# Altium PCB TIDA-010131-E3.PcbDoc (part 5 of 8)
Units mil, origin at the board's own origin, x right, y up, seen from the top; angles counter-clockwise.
Board outline 6889.76 x 5118.11 mil, 6 copper layers (Top Layer, GND Layer, Signal Layer 1, Signal Layer 2, PWR Layer, Bottom Layer), stack 58.5 mil thick; 758 components, 455 nets, 2194 pads, 1156 vias.
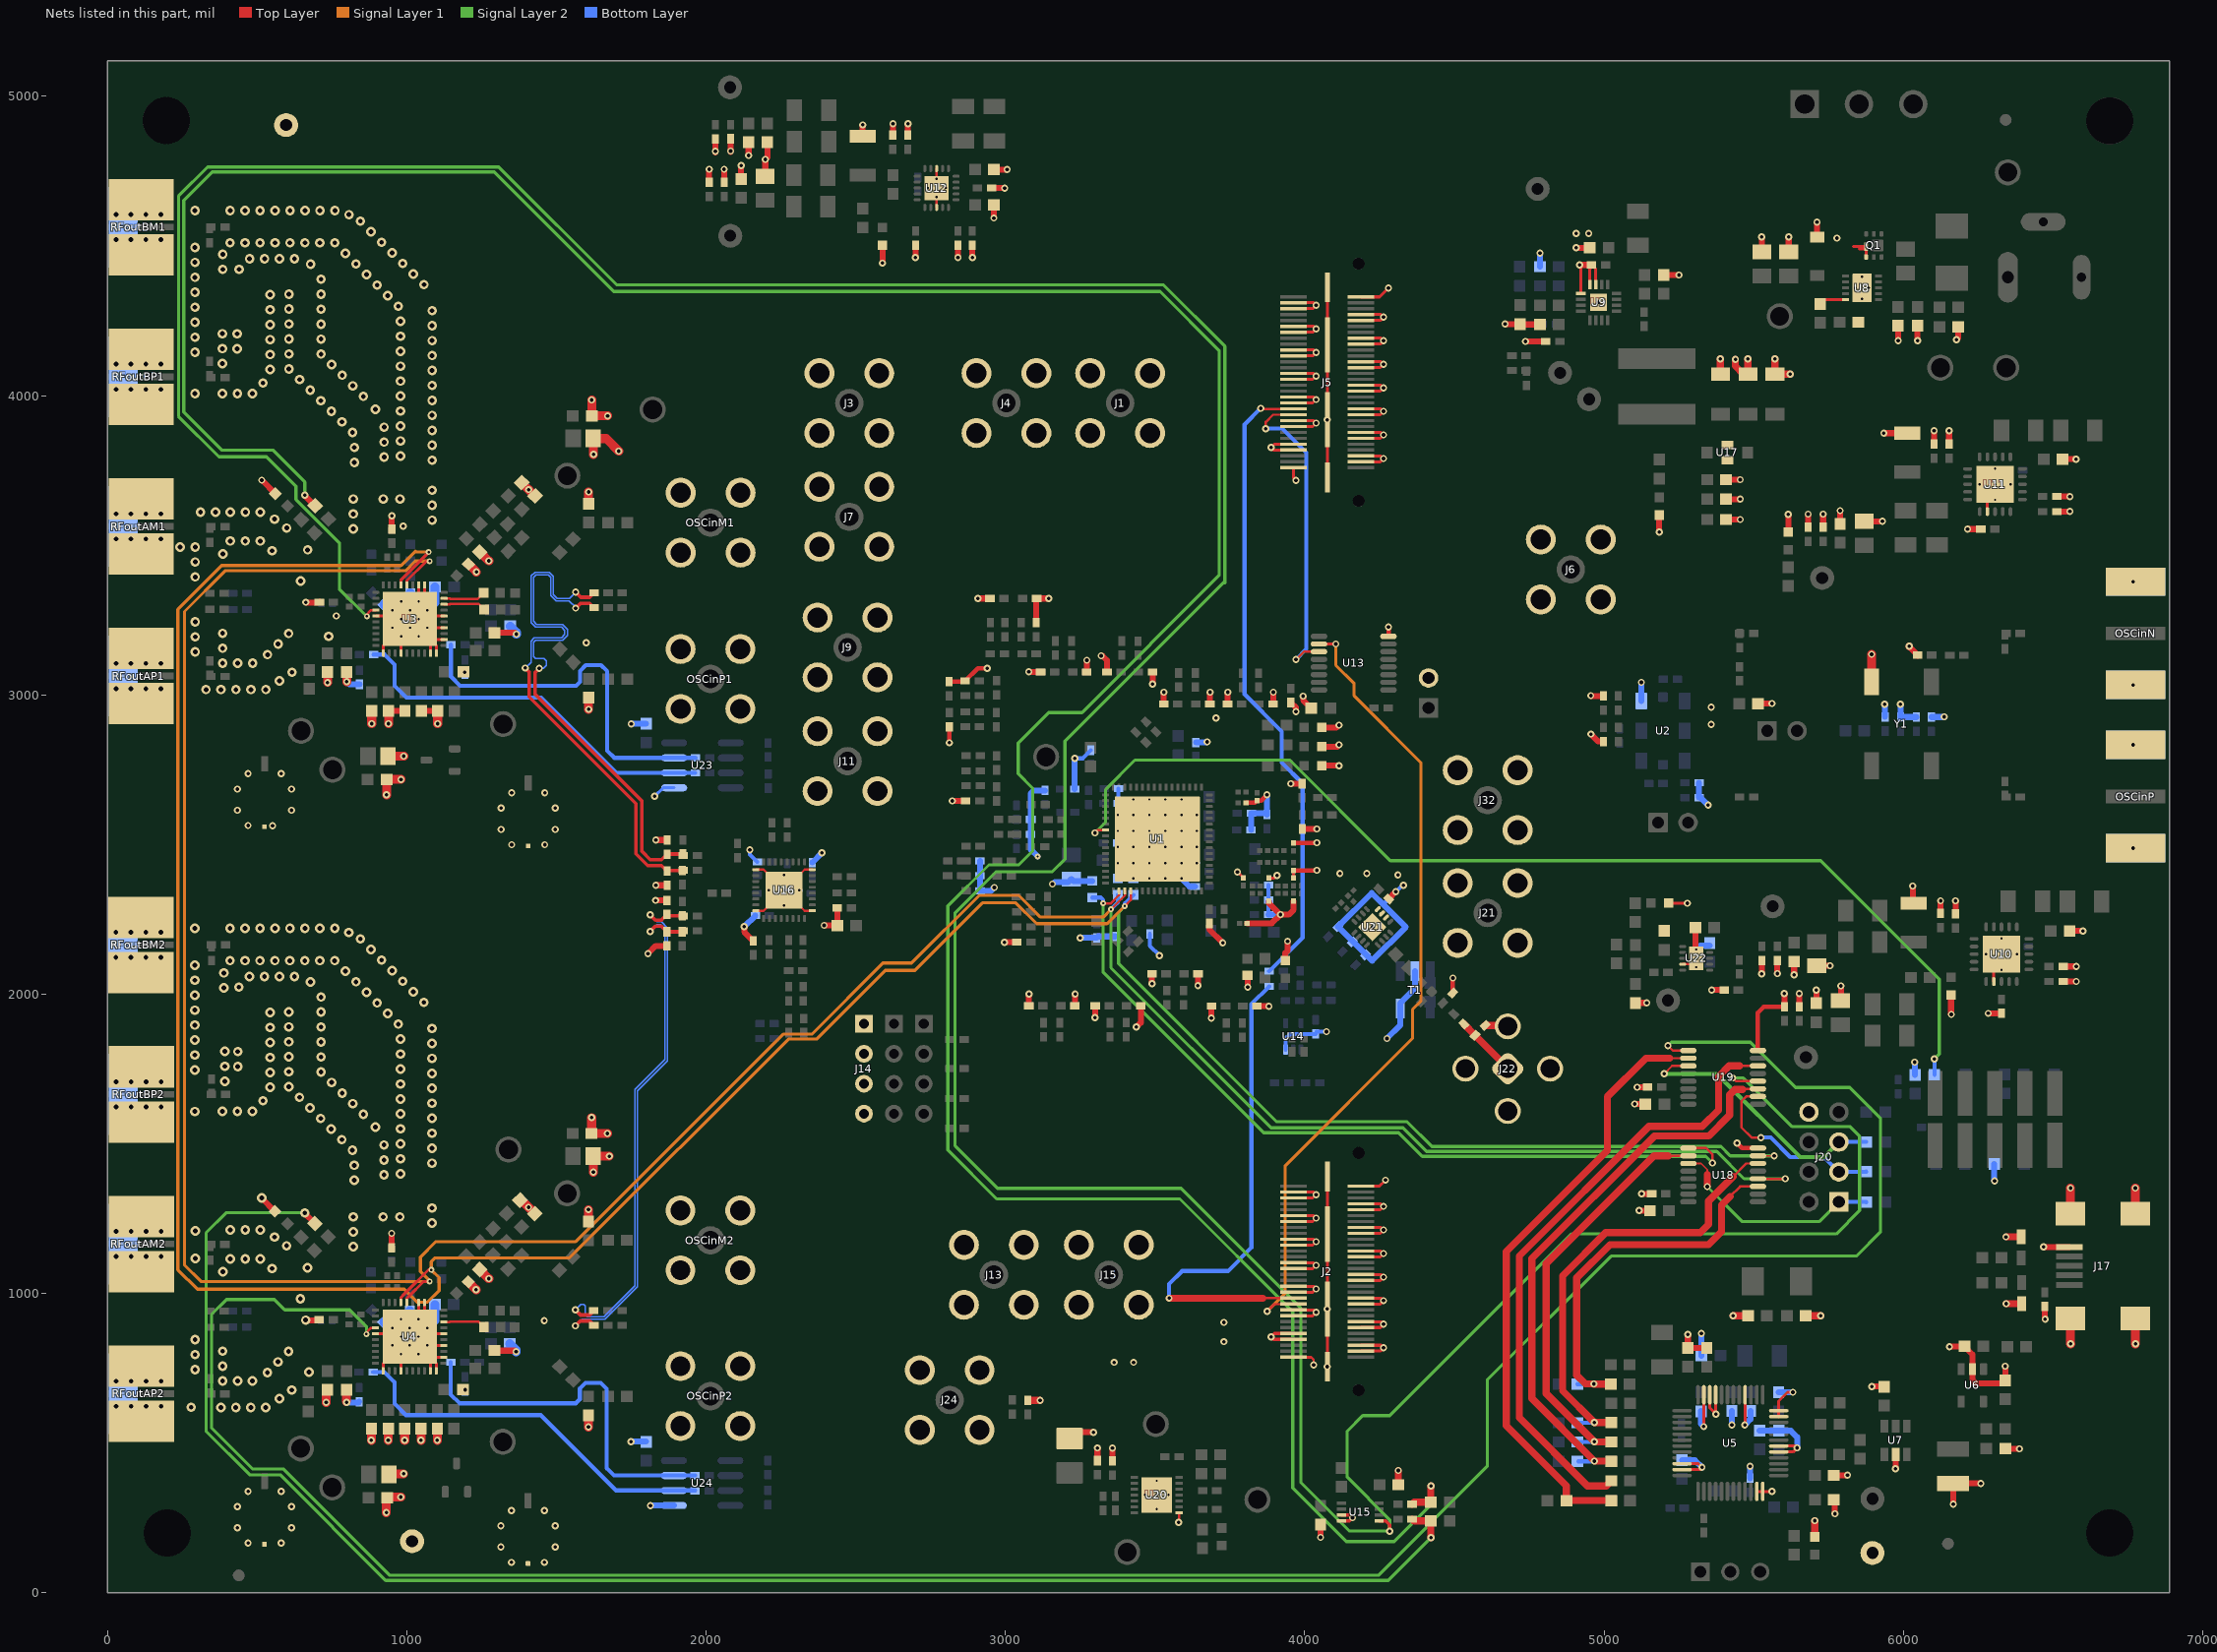
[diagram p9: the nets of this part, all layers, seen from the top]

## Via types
v1: diameter 24, hole 12, Top Layer to Bottom Layer, 726 vias
v2: diameter 32, hole 16, Top Layer to Bottom Layer, 311 vias
v3: diameter 19.68, hole 7.87, Top Layer to Bottom Layer, 117 vias
v4: diameter 25, hole 10, Top Layer to Bottom Layer, 2 vias

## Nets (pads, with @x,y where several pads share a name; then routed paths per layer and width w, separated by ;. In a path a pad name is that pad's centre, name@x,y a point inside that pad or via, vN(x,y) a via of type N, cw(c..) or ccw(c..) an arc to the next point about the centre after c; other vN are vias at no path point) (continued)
GND: C1.1 C2.2 C7.2 C10.1 C11.1 C13.2 C14.2 C18.1 C19.1 C20.1 C21.1 C22.1 C23.1 C26.2 C28.2 C30.1 C31.2 C32.2 C33.2 C34.2 C35.2 C36.2 C37.2 C38.2 C39.2 C40.2 C42.2 C43.2 C45.1 C46.1 C47.1 C49.2 C50.1 C51.1 C52.1 C53.1 C54.1 C55.1 C56.1 C58.1 C59.2 C61.1 C62.2 C63.1 C65.2 C66.1 C67.2 C68.2 C69.1 C70.1 C73.2 C74.2 C75.2 C76.2 C78.1 C79.1 C80.1 C82.2 C83.1 C84.1 C85.1 C86.1 C87.1 C88.1 C89.1 C91.1 C92.2 C94.1 C95.2 C96.1 C98.2 C99.1 C100.2 C101.2 C102.1 C103.1 C106.2 C107.1 C108.2 C109.2 C110.2 C111.2 C112.2 C113.1 C114.2 C115.1 C116.2 C117.2 C118.2 C119.2 C120.1 C121.2 C122.2 C123.1 C124.1 C125.1 C126.2 C127.2 C128.2 C129.2 C130.2 C132.2 C133.2 C134.2 C135.2 C136.2 C137.2 C138.2 C139.2 C140.2 C141.2 C142.2 C143.1 C144.2 C145.2 C146.2 C147.1 C148.2 C149.2 C150.2 C151.2 C152.1 C153.2 C154.2 C155.2 C156.2 C157.2 C158.2 C159.1 C160.2 C161.2 C163.1 C164.2 C165.2 C166.2 C167.1 C168.2 C169.1 C170.2 C171.2 C172.2 C176.1 C177.1 C178.1 C180.1 C181.1 C182.1 C183.2 C184.2 C185.2 C186.1 C187.1 C188.1 C189.2 C190.1 C191.1 C192.1 C193.1 C194.1 C195.1 C196.2 C197.2 C198.1 C199.2 C200.2 C201.2 C202.2 C205.2 C206.2 C208.2 C209.1 C211.1 C212.1 C213.1 D1.2 D2.2 D3.2 D4.2 D5.2 D6.2 D7.1 D9.2 D10.2 D11.2 D12.1 D13.2 D14.2 D15.2 D17.2 J1.2 J1.3 J1.4 J1.5 J2.2 J2.3 J2.5 J2.8 J2.10 J2.11 J2.13 J2.16 J2.18 J2.19 J2.21 J2.24 J2.26 J2.27 J2.29 J2.32 J2.34 J2.35 J2.37 J2.40 J2.42 J2.43 J2.45 J2.48 J2.50 J2.51 J2.53 J2.56 J2.58 J2.59 J2.MP1 J2.MP2 J2.MP3 J2.MP4 J3.2 J3.3 J3.4 J3.5 J4.2 J4.3 J4.4 J4.5 J5.2 J5.3 J5.5 J5.8 J5.10 J5.11 J5.13 J5.16 J5.18 J5.19 J5.21 J5.24 J5.26 J5.27 J5.29 J5.32 J5.34 J5.35 J5.37 J5.40 J5.42 J5.43 J5.45 J5.48 J5.50 J5.51 J5.53 J5.56 J5.58 J5.59 J5.MP1 J5.MP2 J5.MP3 J5.MP4 J6.2 J6.3 J6.4 J6.5 J7.2 J7.3 J7.4 J7.5 J9.2 J9.3 J9.4 J9.5 J11.2 J11.3 J11.4 J11.5 J13.2 J13.3 J13.4 J13.5 J14.1 J14.2 J14.3 J14.4 J15.2 J15.3 J15.4 J15.5 J17.5 J17.Shell J18.2 J20.8 J21.2 J21.3 J21.4 J21.5 J22.2 J22.3 J22.4 J22.5 J24.2 J24.3 J24.4 J24.5 J26.2 J27.2 J28.2 J32.2 J32.3 J32.4 J32.5 J33.2 OSCinM1.2 OSCinM1.3 OSCinM1.4 OSCinM1.5 OSCinM2.2 OSCinM2.3 OSCinM2.4 OSCinM2.5 OSCinN.2 OSCinN.3 OSCinN.4 OSCinN.5 OSCinP1.2 OSCinP1.3 OSCinP1.4 OSCinP1.5 OSCinP2.2 OSCinP2.3 OSCinP2.4 OSCinP2.5 OSCinP.2 OSCinP.3 OSCinP.4 OSCinP.5 Q1.4 Q1.7 R11.1 R12.1 R15.1 R16.1 R17.1 R18.1 R23.1 R24.1 R26.1 R28.1 R34.1 R35.1 R40.1 R52.1 R53.1 R58.1 R59.1 R60.1 R61.1 R64.1 R65.1 R66.1 R67.1 R69.1 R72.2 R75.1 R76.1 R96.2 R104.2 R113.1 R129.2 R138.2 R146.1 R153.2 R167.1 R169.1 R170.1 R171.1 R174.1 R175.1 R176.1 R177.1 R179.1 R180.1 R204.1 R208.1 R211.2 R213.2 R214.2 R215.2 R216.2 R221.2 R230.1 R232.1 R245.1 R246.1 R247.1 R248.1 R270.1 R272.1 R273.1 R285.1 R291.2 R295.1 R297.2 R298.2 R304.1 R313.1 R314.1 R315.1 R324.1 R329.2 R332.1 R337.1 R339.1 R344.1 R345.1 R346.2 R347.2 R356.1 R357.1 R366.1 R367.1 RFoutAM1. RFoutAM1.2 RFoutAM1.3 RFoutAM1.4 RFoutAM2. RFoutAM2.2 RFoutAM2.3 RFoutAM2.4 RFoutAP1. RFoutAP1.2 RFoutAP1.3 RFoutAP1.4 RFoutAP2. RFoutAP2.2 RFoutAP2.3 RFoutAP2.4 RFoutBM1. RFoutBM1.2 RFoutBM1.3 RFoutBM1.4 RFoutBM2. RFoutBM2.2 RFoutBM2.3 RFoutBM2.4 RFoutBP1. RFoutBP1.2 RFoutBP1.3 RFoutBP1.4 RFoutBP2. RFoutBP2.2 RFoutBP2.3 RFoutBP2.4 T1.2 T1.4 TP1.1 TP2.1 TP16.1 U1.65 U2.3@5124.24,2979.81 U3.2 U3.4 U3.6 U3.13 U3.14 U3.25 U3.31 U3.34 U3.39 U3.40 U3.41 U4.2 U4.4 U4.6 U4.13 U4.14 U4.25 U4.31 U4.34 U4.39 U4.40 U4.41 U5.4 U5.9 U5.10 U5.11 U5.22 U5.23 U5.35 U5.36 U5.41 U5.42 U5.47 U5.48 U6.2 U7.2 U8.11 U9.3 U9.4 U9.5 U9.17 U10.7 U10.21 U11.7 U11.21 U12.8 U12.18 U12.21 U13.8 U14.3 U15.3 U15.4 U16.1 U16.8 U16.17 U16.24 U16.33 U17.2 U18.8 U19.8 U20.8 U20.15 U21.6 U21.7 U21.8 U21.17 U22.4 U22.11 U23.5 U24.5 Y1.2 | length 26180.7
  Top Layer w7.5: 4021.5,787.21 4030,778.71 v1(4030,761)
  Top Layer w8: U16.8@2166.12,2278.5 2191.71,2278.5 v3(2260.61,2347.39) ; U16.1@2166.12,2416.29 2191.71,2416.29 v3(2260.61,2347.39) ; U16.17@2355.09,2278.5 2329.5,2278.5 v3(2260.61,2347.39) ; U16.24@2355.09,2416.29 2329.5,2416.29 v3(2260.61,2347.39) ; U12.8@2770.46,4628.71 v3(2770.46,4663.16) U12.21@2770.46,4693.67 v3(2770.46,4724.18) U12.18@2770.46,4758.63 ; v1(3579.05,234.81) 3579.7,234.81 3580.38,235.49 U20.8@3580.38,267.74 ; v1@4785.48,4475.16 v1(4785.98,4475.66) ; U22.4@5262.72,2100.11 5288.31,2100.11 U22.11@5307.99,2119.8
  Top Layer w9.84: U4.25@896.27,864.99 1000.6,864.99 U4.41@1010.45,855.14 ; U3.25@896.53,3263.39 1000.86,3263.39 U3.41@1010.7,3253.55 ; U4.31@921.86,740.97 921.86,766.56 U4.41@980.92,825.62 ; U3.31@922.12,3139.37 922.12,3164.96 U3.41@981.18,3224.02 ; U4.34@980.92,740.97 U4.41@980.92,825.62 ; U3.34@981.18,3139.37 U3.41@981.18,3224.02 ; U4.14@1039.97,969.32 U4.41@1039.97,884.67 ; U3.14@1040.23,3367.72 U3.41@1040.23,3283.07 ; U4.13@1059.66,969.32 1059.66,904.36 U4.41@1039.97,884.67 ; U3.13@1059.92,3367.72 1059.92,3302.76 U3.41@1040.23,3283.07 ; U4.39@1079.34,740.97 U4.41@1079.34,786.25 ; U3.39@1079.6,3139.37 U3.41@1079.6,3184.65 ; U4.40@1099.03,740.97 1099.03,766.56 U4.41@1079.34,786.25 ; U3.40@1099.29,3139.37 1099.29,3164.96 U3.41@1079.6,3184.65 ; U4.2@1124.62,786.25 U4.41@1079.34,786.25 ; U4.4@1124.62,825.62 U4.41@1039.97,825.62 ; U4.6@1124.62,864.99 U4.41@1020.29,864.99 ; U3.2@1124.88,3184.65 U3.41@1079.6,3184.65 ; U3.4@1124.88,3224.02 U3.41@1040.23,3224.02 ; U3.6@1124.88,3263.39 U3.41@1020.55,3263.39 ; U4.41@980.92,825.62 U4.41@1010.45,855.14 ; U3.41@981.18,3224.02 U3.41@1010.7,3253.55 ; U4.41@1010.45,855.14 U4.41@1020.29,864.99 ; U4.41@1010.45,855.14 U4.41@1039.97,825.62 ; U3.41@1010.7,3253.55 U3.41@1040.23,3224.02 ; U3.41@1010.7,3253.55 U3.41@1020.55,3263.39 ; U4.41@1020.29,864.99 U4.41@1039.97,884.67 ; U3.41@1020.55,3263.39 U3.41@1040.23,3283.07 ; U4.41@1039.97,825.62 U4.41@1079.34,786.25 ; U3.41@1040.23,3224.02 U3.41@1079.6,3184.65
  Top Layer w10: C159.1@2117.29,4723.97 C159.1@2125.8,4732.47 ; v1(3775,2408) 3775.99,2408 C30.1@3795,2388.99 ; R273.1@3881,2387.98 3898.98,2387.98 v1(3908,2397) ; J2.59@3962.72,787.21 4021.5,787.21 ; J2.53@3962.72,846.65 3895.94,846.65 v1(3887.47,855.12) 3898.7,866.34 J2.51@3962.72,866.34 ; J2.45@3962.72,925.39 4026.75,925.39 v1(4037.97,936.62) 4029.51,945.08 J2.43@3962.72,945.08 ; J2.37@3962.72,1004.13 4026.75,1004.13 v1(4037.97,1015.36) 4029.51,1023.82 J2.35@3962.72,1023.82 ; J2.29@3962.72,1082.87 4026.75,1082.87 v1(4037.97,1094.1) 4029.51,1102.56 J2.27@3962.72,1102.56 ; J2.21@3962.72,1161.61 4026.75,1161.61 v1(4037.97,1172.84) 4029.51,1181.3 J2.19@3962.72,1181.3 ; J2.13@3962.72,1240.35 4026.75,1240.35 v1(4037.97,1251.58) 4029.51,1260.04 J2.11@3962.72,1260.04 ; J2.5@3962.72,1319.09 4026.75,1319.09 v1(4037.97,1330.32) 4029.51,1338.78 J2.3@3962.72,1338.78 ; J5.59@3962.72,3758.94 3962.72,3724.91 v1(3970.97,3716.66) ; J5.53@3962.72,3818 3895.94,3818 v1(3887.47,3826.46) 3898.7,3837.68 J5.51@3962.72,3837.68 ; J5.45@3962.72,3896.74 4026.75,3896.74 v1(4037.97,3907.96) 4029.51,3916.42 J5.43@3962.72,3916.42 ; J5.37@3962.72,3975.48 4026.75,3975.48 v1(4037.97,3986.7) 4029.51,3995.16 J5.35@3962.72,3995.16 ; J5.29@3962.72,4054.22 4026.75,4054.22 v1(4037.97,4065.44) 4029.51,4073.9 J5.27@3962.72,4073.9 ; J5.21@3962.72,4132.96 4026.75,4132.96 v1(4037.97,4144.18) 4029.51,4152.64 J5.19@3962.72,4152.64 ; J5.13@3962.72,4211.7 4026.75,4211.7 v1(4037.97,4222.92) 4029.51,4231.38 J5.11@3962.72,4231.38 ; J5.5@3962.72,4290.44 4026.75,4290.44 v1(4037.97,4301.66) 4029.51,4310.12 J5.3@3962.72,4310.12 ; R272.1@3963,2387.99 R69.1@3963,2413.64 ; v1(4075.52,755.51) v1(4075.52,948.03) J2.MP2@4075.52,1198.03 J2.MP1@4075.52,1390.55 ; J5.MP4@4075.52,3726.85 v1(4075.52,3919.37) J5.MP2@4075.52,4169.37 J5.MP1@4075.52,4361.89 ; U15.4@4123,240.13 4149.13,240.13 v1(4160,251) 4151.17,259.83 U15.3@4123,259.83 ; J2.58@4188.32,807.28 4252.34,807.28 v1(4263.56,818.51) 4255.1,826.97 J2.56@4188.32,826.97 ; J2.50@4188.32,886.02 4252.34,886.02 v1(4263.56,897.25) 4255.1,905.71 J2.48@4188.32,905.71 ; J2.42@4188.32,964.76 4252.34,964.76 v1(4263.56,975.99) 4255.1,984.45 J2.40@4188.32,984.45 ; J2.34@4188.32,1043.5 4252.34,1043.5 v1(4263.56,1054.73) 4255.1,1063.19 J2.32@4188.32,1063.19 ; J2.26@4188.32,1122.24 4252.34,1122.24 v1(4263.56,1133.47) 4255.1,1141.93 J2.24@4188.32,1141.93 ; J2.18@4188.32,1200.98 4252.34,1200.98 v1(4263.56,1212.21) 4255.1,1220.67 J2.16@4188.32,1220.67 ; J2.10@4188.32,1279.72 4252.34,1279.72 v1(4263.56,1290.95) 4255.1,1299.41 J2.8@4188.32,1299.41 ; J2.2@4188.32,1358.46 4249.78,1358.46 v1(4269.97,1378.66) ; J5.58@4188.32,3778.63 4252.34,3778.63 v1(4263.56,3789.85) 4255.1,3798.31 J5.56@4188.32,3798.31 ; J5.50@4188.32,3857.37 4252.34,3857.37 v1(4263.56,3868.59) 4255.1,3877.05 J5.48@4188.32,3877.05 ; J5.42@4188.32,3936.11 4252.34,3936.11 v1(4263.56,3947.33) 4255.1,3955.79 J5.40@4188.32,3955.79 ; J5.34@4188.32,4014.85 4252.34,4014.85 v1(4263.56,4026.07) 4255.1,4034.53 J5.32@4188.32,4034.53 ; J5.26@4188.32,4093.59 4252.34,4093.59 v1(4263.56,4104.81) 4255.1,4113.27 J5.24@4188.32,4113.27 ; J5.18@4188.32,4172.33 4252.34,4172.33 v1(4263.56,4183.55) 4255.1,4192.01 J5.16@4188.32,4192.01 ; J5.10@4188.32,4251.07 4252.34,4251.07 v1(4263.56,4262.29) 4255.1,4270.75 J5.8@4188.32,4270.75 ; J5.2@4188.32,4329.81 4250.12,4329.81 v1(4279.97,4359.66) ; v1(4917.97,4436.66) 4922.47,4432.16 U9.5@4922.47,4341.16 ; U9.4@4952.42,4371.11 C40.2@4952.42,4430.73 ; C40.2@4958.35,4436.66 4972.28,4422.73 4972.12,4422.57 U9.3@4972.12,4371.11 ; U9.17@4972.12,4321.31 v1(4981.92,4311.51) ; D17.2@5215.53,2304 v1(5278,2304) ; U5.23@5260.78,411.44 5319.62,411.44 v1(5327.2,419.02) 5315.1,431.12 U5.22@5260.78,431.12 ; v1(5333.2,555.18) 5333.62,555.6 U5.11@5333.62,661.44 ; U5.10@5353.3,661.44 5353.3,617.92 v1@5372.99,598.23 ; U5.9@5372.99,661.44 v1@5372.99,598.23 ; v1(5374.2,597.02) v1@5372.99,598.23 ; v1(5470.2,561.02) 5471.41,562.23 U5.4@5471.41,661.44 ; U5.35@5510.78,338.6 U5.36@5530.47,338.6 5560.78,338.6 v1(5561.2,339.02) ; U5.41@5583.62,470.49 5631.67,470.49 v1(5645.2,484.02) 5639.04,490.18 U5.42@5583.62,490.18 ; U5.47@5583.62,588.6 U5.48@5583.62,608.29 5583.62,640.44 5613.2,670.02 v1(5631.2,670.02) ; 5833.69,4497.87 Q1.7@5875.82,4497.87 ; 5853.34,4489.34 5867.28,4489.34 Q1.7@5875.82,4497.87 ; Q1.4@5875.82,4463.23 Q1.7@5875.82,4497.87 ; U11.7@6280.87,3612.37 6280.87,3678.32 v3(6306.46,3703.91) ; U10.7@6302.31,2042.12 U10.21@6302.31,2108.07
  Top Layer w12: v1(4226,2224) U21.17@4226,2238.23
  Top Layer w15: R366.1@2812.31,3044.18 2862.93,3044.18 R339.1@2865.76,3047 2907.76,3089 v1(2939,3089) ; v1(2813,2840) R367.1@2813,2893.38 ; C7.2@3803.57,2639.78 3833.57,2639.78 R28.1@3840.57,2646.79 3854.79,2646.79 v1@3871.66,2663.66 ; R69.1@3962.97,2413.67 v1@4041,2413.67 ; R204.1@3962.97,2505.64 v1@4041,2505.64 ; U13.8@4280,3195.54 v1@4280,3226.97 ; R76.1@4494.7,2003.7 4494.7,2053.7 v1(4495,2054) ; v1(5444,1502) 5460.46,1485.54 U18.8@5514.28,1485.54 ; U19.8@5514.14,1811.57 5514.14,1938.37 5533.86,1958.09 C145.2@5602.62,1958.09
  Top Layer w20: v2(515.39,1319.14) D6.2@559.89,1274.64 D6.2@560.39,1274.14 ; v1(515.65,3717.55) D5.2@560.65,3672.55 ; v2(662.39,911.14) 663.4,910.13 C78.1@709.35,910.13 ; v1(662.65,3309.55) 663.66,3308.54 C45.1@709.6,3308.54 ; C78.1@707.82,911.66 C78.1@709.35,913.18 ; C45.1@708.08,3310.06 C45.1@709.6,3311.58 ; C84.1@928.4,319.74 C84.1@931.84,319.74 ; C51.1@929.16,2717.64 C51.1@932.6,2717.64 ; C70.1@939.4,2945.85 C58.1@994.1,2945.85 ; C94.1@950.02,1155.97 v1@950.02,1200.27 ; C61.1@950.28,3554.38 v1(950.28,3598.67) ; C65.2@1048.5,2945.85 C56.1@1103.4,2945.85 ; C101.2@1292.94,808.94 1361.88,808.94 v1(1365.58,805.24) v1@1366.08,804.74 ; C68.2@1293.2,3207.35 1362.14,3207.35 v1(1366.34,3203.15) ; v1(1806,2135.34) 1831.94,2161.28 R245.1@1869.32,2161.28 ; v1(1831.82,2313.41) 1831.94,2313.53 R246.1@1869.32,2313.53 ; v1(1832.32,2363.66) 1832.44,2363.78 R247.1@1869.82,2363.78 ; v1(1832.32,2514.91) 1832.44,2515.03 R248.1@1869.82,2515.03 ; C161.2@2010.48,4712.32 v1(2010.48,4756.52) ; v1@2031.08,4813.04 v1(2031.08,4816.04) C164.2@2031.08,4857.25 ; C160.2@2060.48,4712.32 v1(2060.48,4756.52) ; v1@2082.08,4814.04 v1(2082.08,4817.04) C183.2@2082.08,4858.25 ; C159.1@2117.29,4723.97 v1(2117.29,4768.18) ; v1(2127.82,2225.41) 2127.82,2208.03 C165.2@2157.32,2178.53 ; v1(2142.08,4802.17) C182.1@2142.08,4846.37 ; C158.2@2197.29,4732.47 2198,4733.18 v1(2198,4789) 2205.08,4796.08 C163.1@2205.08,4846.37 ; v1(2394.32,2229.91) 2437.82,2229.91 C76.2@2438.2,2229.53 ; C130.2@2438.2,2287.91 C76.2@2438.2,2229.53 ; C76.2@2438.32,2229.41 C76.2@2438.2,2229.53 ; C157.2@2523,4866.22 2523,4903.7 v1(2523.79,4904.49) ; v1(2589.5,4442.61) D15.2@2589.5,4502.08 ; C156.2@2624,4869.88 2624,4907.37 v1(2624.79,4908.15) ; C155.2@2674,4869.88 2674,4907.37 v1(2674.79,4908.15) ; R295.1@2699.71,4502.88 2699.71,4461.23 v1(2699.79,4461.15) ; v1(2822.97,2645.66) R285.1@2867.35,2645.66 ; R180.1@2841.71,4502.88 2841.71,4461.23 v1(2841.79,4461.15) ; R179.1@2889.71,4502.88 2889.71,4461.23 v1(2889.79,4461.15) ; v1(2908,3322) R357.1@2948.38,3322 ; C181.1@2953.62,4693.5 v1(2997.83,4693.5) ; v1(2961.5,4593.29) C180.1@2961.5,4637.5 ; C154.2@2961.5,4755.26 v1(3005.7,4755.26) ; v1(2996.97,2172.66) 2997.97,2173.66 R291.2@3038.35,2173.66 ; v1(3078.14,3076.8) 3078.55,3076.4 R11.1@3117.75,3076.4 ; R59.1@3078.38,1960.84 3078.38,2000.04 v1(3078.79,2000.45) ; R337.1@3103,3241.24 3103,3320.38 R356.1@3104.62,3322 v1(3145,3322) ; C201.2@3214.51,515.34 3235.28,536.1 v1(3294.31,536.1) ; R58.1@3232.63,1960.84 3232.63,2000.04 v1(3233.03,2000.45) ; R12.1@3272,3076.4 3272,3115.6 v1(3272.4,3116.01) ; v1(3299.79,1921.57) 3300.2,1921.98 R65.1@3300.2,1961.18 ; C200.2@3307.51,441.48 v1(3307.51,483.93) ; v1(3319.97,3130.66) 3324.16,3130.66 3339.57,3115.25 R15.1@3339.57,3076.05 ; C202.2@3357.51,440.48 v1(3357.51,482.93) ; v1(3437.25,1890) 3452.44,1905.19 R64.1@3452.44,1961.18 ; v1(3489.57,2035) R67.1@3489.57,2067.84 ; v1(3491.4,3036.44) 3491.81,3036.85 R16.1@3491.81,3076.05 ; R17.1@3528.94,2969.4 3528.94,3008.6 v1(3529.35,3009.01) ; v1(3643.41,2028.23) 3643.82,2028.63 R66.1@3643.82,2067.84 ; C186.1@3681.58,2236.53 3681.58,2216.28 v1(3726.2,2171.66) ; R18.1@3683.19,2969.4 3683.19,3008.6 v1(3683.6,3009.01) ; v1(3688.01,1920.47) 3688.42,1920.88 R61.1@3688.42,1960.08 ; R23.1@3742.35,2969.15 3742.35,3008.35 v1(3742.76,3008.76) ; R52.1@3807.96,2236.66 3889.45,2236.66 v1(3918.57,2265.78) ; R53.1@3809.19,2062.84 3809.19,2028.92 3809.72,2028.39 v1(3809.72,2023.39) ; R60.1@3840.67,1960.08 3879.87,1960.08 v1(3880.28,1959.68) ; R72.2@3881,2311 3881,2303.36 v1(3918.57,2265.78) ; R24.1@3894.6,2969.15 3894.6,3008.35 v1(3895.01,3008.76) ; D3.2@3935.19,2111.92 3935.19,2137.19 3943,2145 v1(3943,2177) ; v1(3953.64,2703.31) C11.1@3991.22,2703.31 C11.1@3991.35,2703.43 ; R208.1@3953.64,2974.44 3970.97,2957.1 v1(3970.97,2943.66) ; R26.1@3963,2311 3963,2282 3946.78,2265.78 v1(3918.57,2265.78) ; C22.1@3993.16,2551.38 3993.04,2551.25 3992.63,2551.66 3992.97,2552 v1(4041,2552) ; v1(3995,2996) 3995,2982.5 C1.1@4022.5,2955 ; v1(4053,185) R315.1@4053,227.5 ; D4.2@4057.4,2763.58 v1(4114.26,2763.58) ; D1.2@4057.56,2832.95 4063.51,2827 4108.47,2827 v1(4114.82,2833.35) ; D2.2@4065.5,2890 4105.59,2890 v1(4114.37,2898.78) ; C209.1@4280.7,2318.3 v1(4304.41,2342) ; v1(4669.47,4239.16) C75.2@4719.97,4239.16 ; C75.2@4721.48,4237.66 R232.1@4785.48,4237.66 ; v1(4738,4181) C74.2@4805.38,4181 ; v1(4906.97,4493.66) C129.2@4952.48,4493.66 ; v1(4917.97,4436.66) C40.2@4958.35,4436.66 C40.2@4952.42,4430.73 ; v1(4955.72,2997.39) 4956.89,2996.22 R34.1@4998.07,2996.22 ; v1(4956,2869) 4981.02,2843.98 R40.1@4998.07,2843.98 ; v1(5102.17,1633.1) 5138.33,1633.1 C198.1@5138.67,1632.76 ; R332.1@5105,1970.5 5105.5,1971 v1(5143,1971) ; v1(5111,1689.27) R314.1@5144.38,1689.27 ; v1(5117,1277) 5153.17,1277 C23.1@5153.5,1276.66 ; v1(5126,1333) R313.1@5159.38,1333 ; D11.2@5184.3,3600.81 5184.3,3544.7 v1(5185,3544) ; R221.2@5199.97,4403.16 5251.47,4403.16 v1(5250.97,4402.66) ; v1(5280.2,863.02) C114.2@5280.2,818.51 C112.2@5343.2,818.51 ; C205.2@5305.49,2222.8 5305.49,2122.3 U22.11@5307.99,2119.8 ; v1(5360,2014) R329.2@5401.38,2014 ; C195.1@5407.5,3586 v1(5455,3586) ; C123.1@5407.5,3654 v1(5455,3654) ; C194.1@5407.5,3719 v1(5455,3719) ; R270.1@5514.47,2970.66 5560.97,2970.66 v1(5561.47,2971.16) ; v1(5526.7,4530.23) 5527.18,4529.75 C128.2@5527.18,4480.01 ; v1(5527,2068.17) C197.2@5527,2112.38 ; v1(5579,2068.66) C153.2@5579,2112.87 ; C145.2@5602.62,1958.09 v1(5602.62,2002.3) ; D13.2@5615.85,3544.51 v1(5615.85,3602.98) ; v1(5616.7,4530.23) 5617.18,4529.75 C127.2@5617.18,4480.01 ; v1(5635,2064.79) C152.1@5635,2109 ; C144.2@5652.62,1958.09 v1(5652.62,2002.3) ; C149.2@5682.04,3559.82 v1(5682.04,3604.03) ; C143.1@5709.43,1969.75 v1(5709.43,2013.96) ; C196.2@5711,2095 v1(5755.21,2095) ; v1(5711.7,4579.7) 5712.18,4579.22 D9.2@5712.18,4529.48 ; C148.2@5732.04,3559.82 v1(5732.04,3604.03) ; C113.1@5767.7,392.02 5813.19,392.02 v1(5813.7,392.52) ; C115.1@5771.2,310.02 5771.2,264.52 v1(5771.7,264.02) ; C147.1@5788.85,3571.48 v1(5788.85,3615.69) ; C142.2@5789.43,1978.25 5791.43,1980.25 v1(5791.43,2027.63) ; C146.2@5868.85,3579.98 v1(5930.06,3579.98) ; v1(5894.6,688.61) 5895.11,689.11 C124.1@5935.6,689.11 ; v1(5934.79,3874.5) C141.2@6013,3874.46 ; v1(5974.2,414.02) U7.2@5974.2,461.77 ; C133.2@5982.18,4233.52 5982.18,4183.78 v1(5982.66,4183.3) ; v1@6019.35,3161.39 C178.1@6047.35,3133.39 ; v1(6031.43,2361.25) 6031.43,2307.25 C137.2@6034.43,2304.21 ; R167.1@6047.18,4233.52 6047.18,4183.78 v1(6047.66,4183.3) ; C140.2@6103,3838.12 v1(6103,3882.33) ; C136.2@6124.43,2267.87 C136.2@6124.43,2269.86 v1(6124.43,2312.08) ; C139.2@6153,3838.12 v1(6153,3882.33) ; v1(6154,822) 6155,823 C121.2@6204,823 6230.5,796.5 U6.2@6230.5,747.13 6230.5,711.5 6242,700 6331,700 C118.2@6340.5,709.5 6340.5,756.5 v1(6340,757) ; D14.2@6159.36,1996.95 6159.36,1933.48 v1(6160.36,1932.48) ; v1(6167,296) 6166.26,296.74 C119.2@6166.26,365.23 6258.77,365.23 v1(6259,365) ; C135.2@6174.43,2267.87 v1(6174.43,2312.08) ; v1(6178,4187) 6183.68,4192.68 C132.2@6183.68,4230.01 ; v1(6214.76,3553.87) R171.1@6258.96,3553.87 ; v1(6283.43,1935.87) R170.1@6327.64,1935.87 ; C120.1@6340.76,481.4 6387.6,481.4 v1(6388,481) ; v1(6469,1155.98) 6469.99,1154.99 J17.5@6554.77,1154.99 ; C122.2@6473,956.38 6473,915 v1(6474,914) ; R175.1@6512.38,3612.71 v1(6556.59,3612.71) ; R177.1@6512.38,3662.71 v1(6556.59,3662.71) ; C138.2@6532.5,3787.5 v1(6576.7,3787.5) ; R174.1@6533.82,2042.46 v1(6578.02,2042.46) ; R176.1@6533.82,2092.46 v1(6578.02,2092.46) ; C134.2@6555.63,2211.25 v1(6599.84,2211.25)
  Top Layer w24: R324.1@3075,643.24 v1(3116,643.24) ; C199.2@4312.5,361 v1(4312.5,408.5) ; R75.1@4602.7,1895.7 4675.14,1895.7 J22.5@4678.42,1892.42 ; C42.2@5389.03,4071.95 v1(5389,4123) ; v1(5431.2,926.02) 5431.29,925.93 C126.2@5481.02,925.93 ; v1(5439,4121) 5439,4099 5466.05,4071.95 C43.2@5481.03,4071.95 v1(5481,4123) ; v1(5571,4123) C73.2@5571.03,4071.95 v1(5622.08,4071.98) ; C125.1@5674.01,925.93 5723.74,925.93 v1(5723.83,925.84) ; D10.2@5704.2,186.55 v1(5704.2,241.02) ; v1@6019.35,3161.39 v1(6019.35,3162.77) ; C178.1@6047.35,3133.39 C178.1@6047.97,3132.77 ; v1(6343,1189.08) 6343.04,1189.04 D7.1@6394,1189.04 ; v1(6344,966) v1(6344,966) D12.1@6395,965.96
  Top Layer w30: v1(731,636) 731,674.12 C88.1@734.84,677.97 ; v1(735.6,3041.5) C55.1@735.6,3073.54 ; v1@798.95,639.59 C102.1@798.95,678.16 ; v1(799.7,3044.02) C69.1@799.7,3076.06 ; v1@882.25,508.81 C100.2@882.25,547.95 ; v1(883,2903.78) C67.2@883,2942.92 ; v1(931.84,268.1) 931.84,319.74 v1(980.03,319.74) ; v1(932.6,2666) C51.1@932.6,2717.64 v1(980.79,2717.64) ; C85.1@937.79,397.54 v1(989.43,397.54) ; C52.1@938.55,2795.44 v1(990.19,2795.44) ; v1@938.65,508.81 C103.1@938.65,547.95 ; v1(939.4,2903.78) C70.1@939.4,2942.92 ; v1@993.35,508.81 C91.1@993.35,547.95 ; v1@1047.75,508.81 C98.2@1047.75,547.95 ; v1@1102.65,508.81 C89.1@1102.65,547.95 ; v1(1103.4,2903.78) C56.1@1103.4,2942.92 ; C66.1@1191.6,3074.55 1194,3076.94 v1(1194,3075) ; C80.1@1205.93,1038.43 v1(1231.85,1012.52) v1@1232.35,1012.02 ; C47.1@1206.19,3436.83 v1(1232.6,3410.42) ; C95.2@1244.15,1079.43 v1@1274.35,1049.23 ; C62.2@1244.41,3477.83 v1(1274.6,3447.63) ; R129.2@1383.62,1310.84 1384.09,1310.84 v1(1406.87,1288.07) C92.2@1428.72,1266.22 ; R96.2@1383.88,3709.24 1384.35,3709.24 v1(1407.62,3685.97) C59.2@1428.98,3664.62 ; v1@1607.45,553.31 R138.2@1607.45,592.45 ; R146.1@1607.45,1240.44 v1@1607.45,1279.58 ; v1(1607.7,2951.71) R104.2@1607.7,2990.85 ; R113.1@1607.7,3638.84 v1(1607.7,3677.98) ; v1@1617.94,1587.17 1617.94,1533.94 v1@1671.17,1533.94 ; v1(1618.2,3985.57) C54.1@1618.2,3932.35 v1(1671.43,3932.35) ; C86.1@1622.41,1458.64 v1(1676.62,1458.64) ; v1@1623.89,1404.92 C86.1@1623.89,1458.14 ; v1(1624.15,3803.32) 1624.15,3856.55 1666.65,3856.55 v1(1708.65,3814.55) ; C75.2@4719.97,4239.16 C75.2@4721.48,4237.66 ; Y1.2@5893.97,3043.39 v1(5893.97,3135.39) ; v1(6558.41,1352) 6558.7,1351.7 J17.Shell@6558.7,1267.2 ; J17.Shell@6558.7,916.8 6558.7,832.3 v1(6559,832) ; v1(6774.94,1352) 6775.23,1351.7 J17.Shell@6775.23,1267.2 ; J17.Shell@6775.23,916.8 6775.23,832.3 v1(6775.53,832)
  Bottom Layer w10: v1(1828,2661) 1828.47,2661 1856.97,2689.5 U23.5@1893.51,2689.5 ; v3(6306.46,3756.07) 6312.54,3750 C151.2@6351.38,3750
  Bottom Layer w13.5: v1@2148.32,2481.91 v1(2146.32,2481.91) 2146.32,2466.28 C172.2@2171.2,2441.41 ; v1(3232,2788) 3258.56,2788 C33.2@3285.69,2815.13 ; C26.2@3305.57,2188.16 C26.2@3310.18,2192.77 ; v3(3375.94,2598.93) 3377.6,2600.59 R35.1@3377.6,2686.66 ; C31.2@3482.57,2201.16 3482.57,2161.54 v1(3515.11,2129) ; v1@3671.91,2840.91 v1(3674,2843) ; C37.2@3879.2,2265.78 C38.2@3879.2,2314.78 C39.2@3879.2,2364.78 ; U14.3@3936.38,1814.65 3936.38,1853.04 3950.38,1867.03 C2.2@4036.97,1867.03 ; C2.2@4039.97,1874.66 v1(4072.97,1874.66) ; 4267,2295 4267,2304.59 v1(4304.41,2342) 4305,2342 4327,2364 v1(4330,2364) ; C150.2@6370.81,2159.25 6370.81,2142.91 v3(6380.06,2133.66)
  Bottom Layer w20: v1(731,636) v1@732.44,636 ; v1(798.95,636.09) 838.71,636.09 R216.2@841,638.38 ; v1(799.7,3044.02) 808.35,3035.38 R214.2@842,3035.38 ; v1(1194,3075) R213.2@1195,3076 ; v1(1749,504.99) 1749.5,505.5 C193.1@1799,505.5 ; v1(1750,2902.99) 1750.5,2903.5 C192.1@1800,2903.5 ; v1(1814,291) 1814.5,291.5 U24.5@1892.51,291.5 ; v1(2127.82,2225.41) 2127.82,2225.53 C167.1@2164.57,2262.28 ; C168.2@2217.44,2336.91 2218.44,2337.91 C166.2@2218.44,2396.91 ; v3(2260.61,2398.57) 2270.82,2388.36 C169.1@2270.82,2388.28 ; C170.2@2304.2,2336.91 2311.79,2344.5 v3(2311.79,2347.39) ; C171.2@2355.09,2439.91 2386.82,2471.64 v1(2386.82,2472.41) ; R346.2@2915.2,2445.18 R347.2@2915.2,2396.18 2915.2,2345.06 R298.2@2915.6,2344.66 2950.97,2344.66 v1(2962.97,2356.66) ; v3(3108,2460) 3084.41,2483.59 R344.1@3084.41,2533.78 3084.41,2583.4 R345.1@3084.78,2583.78 3084.78,2670.78 3094.9,2680.9 R297.2@3132.84,2680.9 ; v1@3165.21,2374 3209.79,2374 C13.2@3220.57,2384.78 3227.41,2377.95 C18.1@3290.72,2377.95 ; C185.2@3231.52,2685.06 3231.52,2787.52 v1(3232,2788) ; v1(3249.72,2188.39) 3249.95,2188.16 C26.2@3305.57,2188.16 ; C26.2@3310.18,2192.77 C28.2@3365.72,2192.77 ; C20.1@3375.72,2386.95 C21.1@3427.72,2386.95 ; v3(3588.14,2386.73) 3615.09,2359.78 C35.2@3633.95,2359.78 ; C34.2@3632.95,2409.78 3632.95,2431.54 v3(3639.72,2438.3) ; C32.2@3636.57,2840.91 v1@3671.91,2840.91 ; C190.1@3820.6,2548.66 3820.6,2603.66 C191.1@3821.6,2604.66 3869.6,2604.66 C189.2@3873.97,2600.28 v1@3873.97,2665.97 ; C37.2@3879.2,2265.78 v1(3918.57,2265.78) ; v1(4275,1852) 4319,1896 T1.4@4319,1952 4319,1969.6 4369,2019.6 T1.2@4369,2077 ; R230.1@4785.48,4430.66 4785.48,4475.16 v1(4785.98,4475.66) ; U2.3@5124.24,2979.81 5124.24,3041.18 v1(5124.86,3041.81) ; C109.2@5260.78,442.93 5303.29,442.93 v1(5327.2,419.02) ; v3(5307.99,2149.33) 5321.77,2163.11 C208.2@5353.27,2163.11 ; C188.1@5317.6,2706.66 C187.1@5317.6,2656.66 5322.97,2656.66 v1(5347.97,2631.66) ; C108.2@5324.2,606.52 5324.2,564.18 v1(5333.2,555.18) ; v1(5325.2,866.02) 5325.7,865.51 C111.2@5325.7,792.02 ; v1(5427.2,561.02) R153.2@5427.2,607.52 ; v1(5470.2,561.02) 5489.2,580.02 C107.1@5489.2,607.52 ; C116.2@5488.2,383.02 v1(5488.2,423.02) ; C117.2@5520.2,541.51 5520.36,541.36 C106.2@5583.62,541.36 5623.86,541.36 5645.2,520.02 v1(5645.2,484.02) ; C110.2@5583.2,669.51 5630.7,669.51 v1(5631.2,670.02) ; v1(5615.85,3602.98) v1@5616.85,3601.98 ; v1(5937.97,2968.77) 5938.97,2967.77 C177.1@5938.97,2926.39 ; v1(5989.97,2968.39) 5990.97,2967.39 C176.1@5990.97,2926.02 C19.1@6043.97,2926.02 ; v1(6038,1772.87) 6039,1771.87 R211.2@6039,1730.5 ; C10.1@6093.97,2926.02 6135.35,2926.02 v1(6136.35,2927.02) ; R304.1@6304,1432.5 6304,1377 v1(6305,1376) ; C211.1@4111.5,2225.5 4225,2112 4337.5,2224.5 4267,2295 4224,2338 C211.1@4111.5,2225.5
  Bottom Layer w30: C83.1@923.23,904.36 942.81,884.78 v3(951.68,884.78) ; C50.1@923.99,3302.26 943.57,3282.68 v3(952.44,3282.68) ; v3(980.81,913.91) 982.07,913.91 C82.2@1010.95,942.79 ; v3(981.57,3311.81) 982.83,3311.81 C49.2@1011.7,3340.69 ; v3(1068.21,884.78) 1093.94,910.51 C96.1@1093.94,962.79 ; v3(1068.97,3282.68) 1094.7,3308.41 C63.1@1094.7,3360.69 ; C79.1@1344.54,831.94 1365.58,810.9 v1(1365.58,805.24) ; C46.1@1345.3,3229.85 1366.34,3208.8 v1(1366.34,3203.15)
  other v1: 1350.12,101.48 1460.36,101.48 1314.69,152.67 1495.79,152.67 469.88,165.8 580.12,165.8 434.45,216.98 615.55,216.98 1314.69,223.53 1495.79,223.53 1350.12,274.71 1460.36,274.71 434.45,287.85 615.55,287.85 469.88,339.03 580.12,339.03 881.75,509.31 938.15,509.31 992.85,509.31 1047.25,509.31 1102.15,509.31 1606.95,553.81 1195,678 3363.82,769.93 3428.26,769.93 3729.69,838.91 3729.69,903.34 1459.42,909.13 1273.85,1049.73 949.52,1200.77 1606.95,1280.08 1623.39,1405.42 1670.67,1534.44 1617.44,1587.67 3157.36,2367.95 4311.41,2398 4117.41,2403 4207.41,2403 4041,2414 6767.89,2488.01 1350.88,2499.39 1461.12,2499.39 4041,2506 1315.45,2550.57 1496.55,2550.57 469.88,2563.31 552,2563 434.45,2614.49 615.55,2614.49 1315.45,2621.43 1496.55,2621.43 3874,2666 1350.88,2672.61 1461.12,2672.61 434.45,2685.35 615.55,2685.35 469.88,2736.54 580.12,2736.54 6767.89,2833.01 5358.31,2900.91 3703.51,2923.18 5357.93,2958.67 6767.89,3033.01 1599.49,3173.87 4279.97,3227 764.8,3264 6767.89,3378.01 988.65,3563.55 5778,4526 4907,4542 4949,4542
  other v2: 379.09,619.33 429.09,619.33 479.09,619.33 529.09,619.33 279.97,619.97 574.55,648.59 616.3,677.3 384.78,707.36 434.78,707.36 484.78,707.36 534.67,735.99 673.22,737.32 292.91,745.71 384.79,757.36 570.02,771.34 292.91,795.71 384.79,807.36 605.38,806.7 292.91,845.71 644.87,982.02 385.67,1072.58 549.98,1083.15 668.69,1086.03 410.49,1115.61 460.49,1115.61 510.49,1115.61 293.83,1117 821.13,1156.1 598.76,1159.2 558.31,1188.62 821.13,1206.1 293.88,1209.24 410.56,1212.42 460.56,1212.42 510.56,1212.42 1084.57,1235.44 821.13,1256.1 921.13,1256.1 976.97,1256.1 1084.57,1285.44 824.96,1378.17 924.1,1396.14 979.26,1399.95 824.96,1428.17 1084.57,1435.44 924.1,1446.14 979.26,1449.95 818.5,1478.63 1084.57,1485.44 924.1,1496.14 979.26,1499.95 783.15,1513.98 1084.57,1535.44 747.79,1549.34 979.26,1549.95 894.97,1555.59 712.44,1584.69 1084.57,1585.44 854.94,1598.9 979.26,1599.95 292.33,1608.05 384.21,1608.38 434.21,1608.38 484.21,1608.38 677.08,1620.05 819.59,1634.26 1084.57,1635.44 519.56,1643.74 979.26,1649.95 641.73,1655.4 784.23,1669.61 1084.57,1685.44 543.4,1688.68 606.37,1690.76 979.26,1699.95 748.87,1704.97 392.11,1708.82 1084.57,1735.44 543.4,1738.68 713.52,1740.32 606.37,1740.76 292.33,1746.73 979.26,1749.95 435.55,1758.33 392.11,1758.82 1084.57,1785.44 543.4,1788.68 713.52,1790.32 606.37,1790.76 292.33,1796.73 979.26,1799.95 435.55,1808.33 392.11,1808.82 1084.57,1835.44 543.4,1838.68 713.52,1840.32 606.37,1840.76 292.33,1846.73 979.26,1849.95 1084.57,1885.44 543.4,1888.68 713.52,1890.32 606.37,1890.76 292.33,1896.73 971.64,1899.95 936.28,1935.31 543.41,1938.68 713.52,1940.32 606.37,1940.76 292.33,1946.73 900.93,1970.67 1057.23,1972.52 713.52,1990.32 292.33,1996.73 865.57,2006.02 1021.87,2007.88 389.09,2020.85 439.4,2023.34 678.51,2040.56 830.22,2041.38 986.52,2043.23 292.33,2046.73 474.76,2058.7 524.76,2058.7 574.76,2058.7 624.76,2058.7 389.09,2070.85 794.86,2076.73 951.16,2078.59 292.33,2096.73 409.51,2112.09 459.51,2112.09 509.51,2112.09 559.51,2112.09 609.51,2112.09 659.51,2112.09 709.51,2112.09 759.51,2112.09 915.81,2113.94 880.45,2149.3 845.1,2184.65 806.73,2206.23 292.33,2220.01 409.74,2220.01 459.74,2220.01 509.74,2220.01 559.74,2220.01 609.74,2220.01 659.74,2220.01 709.74,2220.01 759.74,2220.01 329.35,3017.73 379.35,3017.73 429.35,3017.73 479.35,3017.73 529.35,3017.73 574.81,3046.99 616.56,3075.7 385.04,3105.76 435.04,3105.76 485.04,3105.76 534.93,3134.39 293.17,3144.11 385.04,3155.76 570.28,3169.74 293.17,3194.11 739.24,3195.46 605.64,3205.1 385.04,3205.76 293.17,3244.11 645.13,3380.42 293.17,3394.11 293.17,3444.11 385.93,3470.98 550.24,3481.56 668.94,3484.43 243.17,3494.11 293.17,3494.11 410.75,3514.02 460.75,3514.01 510.75,3514.01 821.39,3554.5 599.02,3557.6 1084.83,3583.84 558.57,3587.03 821.39,3604.5 310.82,3610.82 360.82,3610.82 410.82,3610.82 460.82,3610.82 510.82,3610.82 1084.83,3633.84 821.39,3654.5 921.39,3654.5 977.23,3654.5 1084.83,3683.84 825.22,3776.58 1084.83,3783.84 924.36,3794.55 979.52,3798.36 825.22,3826.58 1084.83,3833.84 924.36,3844.55 979.52,3848.36 818.76,3877.03 1084.83,3883.84 924.36,3894.55 979.52,3898.36 783.41,3912.38 1084.83,3933.84 748.05,3947.74 979.52,3948.36 895.23,3953.99 712.7,3983.1 1084.83,3983.84 855.2,3997.3 979.52,3998.36 292.59,4006.45 384.47,4006.78 434.47,4006.78 484.47,4006.78 677.34,4018.45 819.84,4032.66 1084.83,4033.84 519.82,4042.14 979.52,4048.36 641.99,4053.81 784.49,4068.01 1084.83,4083.84 543.66,4087.09 606.63,4089.16 979.52,4098.36 749.13,4103.37 384.47,4106.78 1084.83,4133.84 543.66,4137.09 606.63,4139.16 713.78,4138.73 292.59,4145.13 979.52,4148.36 384.47,4156.78 433.51,4156.63 1084.83,4183.84 543.66,4187.09 606.63,4189.16 713.78,4188.73 292.59,4195.13 979.52,4198.36 384.47,4206.78 433.51,4206.63 1084.83,4233.84 543.66,4237.09 606.63,4239.16 713.78,4238.73 292.59,4245.13 979.52,4248.36 1084.83,4283.84 543.66,4287.09 606.63,4289.16 713.78,4288.73 292.59,4295.13 971.9,4298.36 936.54,4333.71 543.66,4337.09 606.63,4339.16 713.78,4338.73 292.59,4345.13 901.19,4369.07 1057.49,4370.92 713.78,4388.73 292.59,4395.13 865.83,4404.42 1022.13,4406.28 385.35,4422 439.66,4421.75 678.77,4438.96 830.48,4439.78 986.78,4441.63 292.59,4445.13 475.02,4457.1 525.02,4457.1 575.02,4457.1 625.02,4457.1 385.35,4472 795.12,4475.13 951.42,4476.99 292.59,4495.13 409.76,4510.49 459.76,4510.49 509.76,4510.49 559.77,4510.49 609.77,4510.49 659.77,4510.49 709.77,4510.49 759.77,4510.49 916.07,4512.35 880.71,4547.7 845.36,4583.06 806.99,4604.63 292.59,4618.41 410,4618.41 460,4618.41 510,4618.41 560,4618.41 610,4618.41 660,4618.41 710,4618.41 760,4618.41
  other v3: 3505.57,279.55 3466.2,326.8 3505.57,326.8 3544.94,326.8 3505.57,374.04 980.81,797.38 1039.08,797.38 951.68,826.51 1009.95,826.51 1068.21,826.51 980.81,855.64 1039.08,855.64 1009.95,884.78 1039.08,913.91 6327.9,2081.49 5307.99,2090.27 6275.73,2133.66 6327.9,2133.66 6327.9,2185.83 2260.61,2296.21 2209.43,2347.39 3427.51,2386.73 3481.05,2386.73 3534.6,2386.73 3375.94,2438.3 3427.51,2438.3 3481.05,2438.3 3534.6,2438.3 3588.14,2438.3 3375.94,2491.84 3427.51,2491.84 3481.05,2491.84 3534.6,2491.84 3588.14,2491.84 3639.72,2491.84 3375.94,2545.39 3427.51,2545.39 3481.05,2545.39 3534.6,2545.39 3588.14,2545.39 3639.72,2545.39 3427.51,2598.93 3481.05,2598.93 3534.6,2598.93 3588.14,2598.93 3639.72,2598.93 3427.51,2650.51 3481.05,2650.51 3534.6,2650.51 3588.14,2650.51 981.57,3195.28 1039.84,3195.28 952.44,3224.41 1010.7,3224.41 1068.97,3224.41 981.57,3253.55 1039.84,3253.55 1010.7,3282.68 1039.84,3311.81 6306.46,3651.74 6254.3,3703.91 6358.63,3703.91 5862.18,4322.61 5839.54,4360.01 5884.82,4360.01 5862.18,4397.41 2739.95,4693.67 2800.98,4693.67
ILIM: R166.2 U8.10 | length 90.7
  Top Layer w10: R166.2@5722.18,4306.51 5736.31,4320.64 U8.10@5807.06,4320.64
ILMK04828_CSB: R157.2 R187.1 U18.10 | length 1397.9
  Top Layer w8: 5215,1459.95 U18.10@5282,1459.95
  Top Layer w24: R157.2@5024.7,504.02 4968.52,504.02 v1(4968.04,504.5) 4807,665.54 4807,1100 5166.95,1459.95 5215,1459.95
  Bottom Layer w13.5: R187.1@4913.7,503.52 4967.05,503.52 v1(4968.04,504.5)
ILMK_LMX_CLK: R154.2 R185.1 U18.3 | length 1289.7
  Top Layer w8: 5421,1324 5454.59,1357.59 U18.3@5514.28,1357.59
  Top Layer w24: R154.2@5022.7,697.52 4966.52,697.52 v1(4966.04,698) 4938,698 4909,727 4909,1052 5020,1163 5349.14,1163 5392.67,1206.53 5392.67,1295.67 5421,1324
  Bottom Layer w13.5: R185.1@4911.7,697.02 4965.05,697.02 v1(4966.04,698)
ILMK_LMX_DATA: R156.2 R186.1 U18.6 | length 1499
  Top Layer w8: 5431.55,1390.55 5475.36,1434.36 U18.6@5514.28,1434.36
  Top Layer w24: R156.2@5024.7,568.52 4968.52,568.52 v1(4968.04,569) 4862,675.04 4862,1059 5006,1203 5322,1203 5349.14,1230.14 5349.14,1308.14 5431.55,1390.55
  Bottom Layer w13.5: R186.1@4913.7,568.02 4967.05,568.02 v1(4968.04,569)
ILMX1_CSB: R158.2 R188.1 U19.3 | length 1904.9
  Top Layer w8: 5463,1682 5464.61,1683.61 U19.3@5514.14,1683.61
  Top Layer w24: R158.2@5024.7,439.52 4968.52,439.52 v1(4968.04,440) 4759,649.04 4759,1117 5168,1526 5350,1526 5420,1596 5420,1663.99 5438.01,1682 5463,1682
  Bottom Layer w13.5: R188.1@4913.7,439.02 4967.05,439.02 v1(4968.04,440)
ILMX2_CSB: R181.2 R206.1 U19.10 | length 2046.1
  Top Layer w8: 5219.98,1785.98 U19.10@5281.86,1785.98
  Top Layer w24: R206.1@4874.5,308 4874.5,357.5 4674,558 4674,1140 5011,1477 5011,1657 5139.98,1785.98 5219.98,1785.98 ; R206.1@4874.5,308 R181.2@5024.7,308.02
ILMX_SDO: R159.2 U19.6 | length 2075.3
  Top Layer w8: 5453.43,1760.39 U19.6@5514.14,1760.39
  Top Layer w24: R159.2@5024.7,374.02 5007.69,357 4945,357 4717,585 4717,1125 5150,1558 5328,1558 5383,1613 5383,1725.31 5418.07,1760.39 5453.43,1760.39
IOVLVL: R210.2 U1.7 | length 3653.7
  Top Layer w8: v1(3299,2539) 3308.14,2548.14 U1.7@3334.6,2548.14
  Signal Layer 2 w10.5: v1(3299,2539) 3335,2575 3335,2684 3433,2782 3950,2782 4286,2446 5724,2446 6120,2050 6120,1799.5 v1(6104,1783.5)
  Bottom Layer w13.5: R210.2@6104,1731 v1(6104,1783.5)
LMK04828_CSB: C18.2 U1.18 U18.9 | length 2776.5
  Top Layer w8: v3(3326.97,2303.66) 3352.35,2303.66 3379.87,2331.19 U1.18@3379.87,2345.39 ; U18.9@5282,1485.54 5341.46,1485.54 5362,1465 v1(5362,1436)
  Signal Layer 2 w10.5: v3(3326.97,2303.66) 3326.97,2072.53 3862.5,1537 4314,1537 4393,1458 5340,1458 v1(5362,1436)
  Bottom Layer w13.5: C18.2@3290.72,2322.83 3318.81,2322.83 3326.97,2314.66 v3(3326.97,2303.66)
LMK04828_RESET1: J5.41 U13.11 | length 1087.4
  Top Layer w8: v1(3869.97,3889.66) 3869.97,3911.66 3894.42,3936.11 J5.41@3962.72,3936.11 ; v1(3971,3118) 3997.36,3144.36 U13.11@4047.72,3144.36
  Bottom Layer w13.5: v1(3869.97,3889.66) 3925.34,3889.66 4005.97,3809.03 4005.97,3152.97 v1(3971,3118)
LMK04828_RESET2: J2.41 U13.10 | length 2713.3
  Top Layer w7.5: v1(3874.97,940.66) 3898.82,964.51 J2.41@3962.72,964.51
  Top Layer w10.5: U13.10@4047.72,3169.95 v1@4103.95,3169.95
  Signal Layer 1 w10.5: v1(3874.97,940.66) 3935,1000.69 3935,1427 4360.5,1852.5 4360.5,1949 4388,1976.5 4388,2774 4164.97,2997.03 4164.97,3038.14 4104,3099.11 v1(4104,3170)
LMK04828_SYNC1: J5.39 R200.1 | length 2140.3
  Top Layer w8: v1(3852.97,3957.66) 3855.08,3955.55 J5.39@3962.72,3955.55
  Bottom Layer w13.5: v1(3852.97,3957.66) 3799,3903.69 3799,3002 3923,2878 3923,2774 3993,2704 3993,2188.54 R200.1@3881.4,2076.94
LMK04828_SYNC2: J2.39 R202.1 | length 1686.3
  Top Layer w8: 3861,984.21 3861.24,984.45 J2.39@3962.72,984.45
  Top Layer w24: v1(3547,984.21) 3861,984.21
  Bottom Layer w13.5: v1(3547,984.21) 3547,1031.66 3590.34,1075 3744.34,1075 3821.97,1152.64 3821.97,1966.51 R202.1@3881.4,2025.94
LMK_CLKIN: J22.1 R73.1 R75.2 | length 210.1
  Top Layer w24: R73.1@4531.7,1900.3 4531.7,1899.89 R75.2@4569.3,1862.3 4678.42,1753.17 J22.1@4678.42,1751
LMK_LMX_CLK: C20.2 U1.19 U3.16 U4.16 U18.4 | length 10062.2
  Top Layer w8: v3(3352.72,2283.39) 3399.56,2330.22 U1.19@3399.56,2345.39 ; U18.4@5514.28,1383.18 v1(5605.18,1383.18)
  Top Layer w9.84: U4.16@1000.6,964.82 1000.6,983.97 1007.79,991.16 1007.79,991.56 1056.25,1040.02 v3(1076.89,1040.02) ; U3.16@1000.86,3367.72 1000.86,3381.78 1066.03,3446.95 v3(1076.36,3446.95)
  Signal Layer 2 w10.5: v3(3352.72,2283.39) 3352.72,2088.28 3887.5,1553.5 4328.5,1553.5 4407.5,1474.5 5376.5,1474.5 5467.82,1383.18 v1(5605.18,1383.18)
  Signal Layer 1 w10.5: v3(1076.36,3446.95) 1028.49,3446.95 996,3414.5 393.5,3414.5 257.5,3278.5 257.5,1095 312.48,1040.02 v3(1076.89,1040.02) 1076.89,1042.19 1045.75,1073.33 1045.75,1121.25 1097.6,1173.1 1564.6,1173.1 2257.75,1866.25 2353.25,1866.25 2591,2104 2686.5,2104 2912.5,2330 3045,2330 3117.5,2257.5 3326.84,2257.5 v3(3352.72,2283.39)
  Bottom Layer w13.5: v3(3352.72,2283.39) 3375.72,2306.39 C20.2@3375.72,2331.83
LMK_LMX_DATA: C21.2 U1.20 U3.17 U4.17 U18.7 | length 10158.8
  Top Layer w6: U18.7@5514.28,1459.95 v1(5568.66,1459.95)
  Top Layer w8: v3(3398.72,2294.39) 3419.24,2314.91 U1.20@3419.24,2345.39
  Top Layer w9.84: U4.17@980.92,969.32 981.27,969.67 981.27,987.04 991.94,997.72 991.94,998.12 1072.82,1079 v3(1082,1079) ; U3.17@981.18,3367.72 981.53,3368.07 981.53,3384.85 v3(1073.68,3477)
  Signal Layer 2 w10.5: v3(3398.72,2294.39) 3378,2273.66 3378,2102 3906,1574 4342,1574 4425,1491 5391,1491 5422.05,1459.95 v1(5568.66,1459.95)
  Signal Layer 1 w10.5: v3(1073.68,3477) 1031.94,3477 1028.97,3479.97 981,3432 382,3432 235.5,3285.5 235.5,1079 300.5,1014 991.5,1014 1034.5,971 1069.5,971 1108,1009.5 1108,1053 v3(1082,1079) 1082,1105.82 1095.18,1119 1544,1119 2274.75,1849.75 2369.25,1849.75 2598.76,2079.26 2697.76,2079.26 2923.5,2305 3035,2305 3104.5,2235.5 3339.84,2235.5 v3(3398.72,2294.39)
  Bottom Layer w13.5: v3(3398.72,2294.39) 3398.72,2302.83 C21.2@3427.72,2331.83
LMK_SCSB: J20.1 R308.2 U18.11 | length 736.2
  Top Layer w6: U18.11@5282,1434.36 5324.64,1434.36 5345,1414 5345,1398.15
  Top Layer w24: v1(5345,1357) 5345,1398.15
  Signal Layer 2 w10.5: v1(5345,1357) 5462,1240 5718.63,1240 J20.1@5784.63,1306
  Bottom Layer w13.5: J20.1@5784.63,1306 5875.5,1306 R308.2@5876.5,1305
LMX1_CSB: U3.24 U15.5 U19.4 | length 14378.8
  Top Layer w8: v3@863.6,3265.87 880.8,3283.07 U3.24@896.53,3283.07 ; v1@5430.35,1720 5441.14,1709.2 U19.4@5514.14,1709.2
  Top Layer w10.5: U15.5@4249,240.13 4270.87,240.13 4284,227 v1(4284,206)
  Signal Layer 2 w10.5: v3(866.79,3262.68) 865.79,3262.68 775,3353.47 775,3508 630,3653 630,3697.19 531.69,3795.5 372.68,3795.5 237.5,3930.68 237.5,4666.32 334.77,4763.59 1307.41,4763.59 1701,4370 3528,4370 3733,4165 3733,3375 3728,3375 3199,2846 3199,2451.19 3156.81,2409 2969,2409 2832,2272 2832,1493 2974,1351 3587.33,1351 3987,951.33 3987,369 4150,206 v1(4284,206) 4284,244 4142,386 4142,540 4194,592 4284,592 4891,1199 5776,1199 5854,1277 5854,1525 5821,1558 5627.49,1558 5465.49,1720 v1(5430,1720)
LMX1_REFN: R165.1 R241.2 R247.2 R264.1 | length 1778.1
  Top Layer w12: v1(1395.65,3089.8) 1409.27,3076.17 1409.27,2993.73 1766,2637 1766,2468.72 1805.31,2429.41 1851.44,2429.41 R247.2@1869.82,2411.03 1872.32,2413.53 R264.1@1921.32,2413.53 ; v1(1564.46,3343.3) 1581.71,3326.05 1611.53,3326.05 R165.1@1626.03,3340.55
  Bottom Layer w4.25: v1(1395.65,3089.8) 1415.02,3109.17 1415.02,3179.76 1426.14,3190.88 1517.24,3190.88 1528.02,3201.66 1528.02,3215.84 1517.24,3226.62 1430.79,3226.62 1415.02,3242.39 1415.02,3397.02 1428,3410 1476,3410 1489.5,3396.5 1489.5,3335.5 1502.95,3322.05 1543.21,3322.05 v1(1564.46,3343.3)
LMX1_REFP: R103.2 R240.2 R248.2 R262.1 | length 1776.9
  Top Layer w12: v1(1442.9,3089.05) 1429.27,3075.42 1429.27,3002.01 1786,2645.28 1786,2477 1813.59,2449.41 1851.44,2449.41 R248.2@1869.82,2467.78 1870.32,2468.28 R262.1@1922.32,2468.28 ; v1(1564.46,3289.8) 1580.71,3306.05 1611.53,3306.05 R103.2@1626.03,3291.55
  Bottom Layer w4.25: v1(1442.9,3089.05) 1457.05,3089.05 1466,3098 1466,3114 1459,3121 1430.52,3121 1423.52,3128 1423.52,3176.24 1429.66,3182.38 1520.76,3182.38 1536.52,3198.14 1536.52,3219.36 1520.76,3235.12 1434.31,3235.12 1423.52,3245.91 1423.52,3393.5 1431.52,3401.5 1472.48,3401.5 1481,3392.98 1481,3331.98 1499.43,3313.55 1542.65,3313.55 1564.46,3291.73 v1(1564.46,3289.8)
LMX1_SCSB: J20.3 R309.2 U19.2 | length 628.4
  Top Layer w8: U19.2@5514.14,1658.02 5475.02,1658.02 5459,1642 5459,1555 5493,1521 v1(5524,1521)
  Bottom Layer w13.5: v1(5524,1521) 5557,1521 5622,1456 5734.63,1456 J20.3@5784.63,1406 5875.5,1406 R309.2@5876.5,1407
LMX1_SDO: R102.2 R189.1 R218.2 | length 10992.1
  Top Layer w20: v1@659.65,3666.13 R102.2@693.94,3631.84
  Top Layer w24: R218.2@4358.62,295.73 4365.62,302.73 R189.1@4421.5,302.73 4421.5,356.5 v1(4422,357)
  Signal Layer 2 w10.5: v1(659.65,3667.55) 659.65,3711.35 553,3818 382,3818 255,3945 255,4652 350.09,4747.09 1292.91,4747.09 1692,4348 3517,4348 3714,4151 3714,3399 3256,2941 3145,2941 3043,2839 3043,2736.54 3091.54,2688 3091.54,2478.54 3045,2432 2945,2432 2808,2295 2808,1479 2971,1316 3583,1316 3960,939 3960,350 4139,171 4299,171 4422,294 v1(4422,357)
LMX1_SYNC: R100.2 R101.1 U23.7 | length 1268.6
  Bottom Layer w13.5: R100.2@1147.76,3167.62 1147.76,3061.24 1178,3031 1566,3031 1579,3044 1579,3080 1598,3099 1649,3099 1669,3079 1669,2814 1693.5,2789.5 U23.7@1893.51,2789.5 R101.1@1964.76,2789.5
LMX1_SYSREFREQ: R99.2 R134.2 U23.6 | length 1280.4
  Bottom Layer w13.5: R99.2@889.24,3134.62 926.38,3134.62 960,3101 960,3030 999,2991 1449,2991 1700.5,2739.5 U23.6@1893.51,2739.5 R134.2@1964.38,2739.5
LMX2_CSB: U4.24 U19.9 | length 8719.3
  Top Layer w8: v3@863.34,867.47 880.55,884.67 U4.24@896.27,884.67 ; v1(5213.62,1828) 5230.06,1811.57 U19.9@5281.86,1811.57
  Signal Layer 2 w10.5: v3(865.53,864.27) 865.53,889.15 809.68,945 592.56,945 557.56,980 398,980 348,930 348,551 486,413 589,413 944,58 4246,58 4610,422 4610,711 5024,1125 5843,1125 5924,1206 5924,1585 5821,1688 5640.33,1688 5488.94,1839.39 5225.01,1839.39 v1(5213.62,1828)
LMX2_REFN: R168.1 R243.2 R245.2 R268.1 | length 1777.9
  Top Layer w12: v1(1563.7,945.39) 1580.95,928.14 1610.49,928.14 R168.1@1624.99,942.64 ; v1(1813.41,2209.41) 1813.41,2209.81 1831,2227.41 1850.44,2227.41 R245.2@1869.32,2208.53 R268.1@1920.32,2208.53
  Bottom Layer w4.25: v1(1563.7,945.39) 1581.31,963 1592,963 1597,958 1597,928.89 1603,922.89 1658.89,922.89 1762.5,1026.5 1762.5,1681 1862.82,1781.32 1862.82,2218 1847.87,2232.95 1836.95,2232.95 v1(1813.41,2209.41)
LMX2_REFP: R137.2 R242.2 R246.2 R266.1 | length 1777.4
  Top Layer w12: v1(1563.7,891.89) 1579.95,908.14 1610.77,908.14 R137.2@1625.27,893.64 ; v1(1813,2265) 1813.41,2265 1831,2247.41 1850.44,2247.41 R246.2@1869.32,2266.28 1873.32,2262.28 R266.1@1921.32,2262.28
  Bottom Layer w4.25: v1(1563.7,891.89) 1586.2,914.39 1662.41,914.39 1771,1022.98 1771,1677.48 1871.32,1777.8 1871.32,2221.52 1851.39,2241.45 1836.55,2241.45 v1(1813,2265)
LMX2_SCSB: J20.5 R310.2 U19.11 | length 903.2
  Top Layer w8: v1(5200.99,1734) 5227.38,1760.39 U19.11@5281.86,1760.39
  Signal Layer 2 w13.5: v1(5200.99,1734) 5377,1734 5655,1456 5734.63,1456 J20.5@5784.63,1506
  Bottom Layer w13.5: J20.5@5784.63,1506 R310.2@5876.5,1506
LMX2_SDO: R135.2 R219.2 R225.1 | length 5548.8
  Top Layer w20: v2@659.39,1267.73 R135.2@693.18,1233.94 R135.2@693.68,1233.44
  Top Layer w24: v2@659.39,1267.73 v2(659.39,1269.14) ; R219.2@4358.62,245.73 4364.62,239.73 R225.1@4421.5,239.73 4421.5,184.5 v1(4422,184)
  Signal Layer 2 w10.5: v2@658.89,1269.64 396.64,1269.64 330,1203 330,539 475,394 577,394 929.5,41.5 4279.5,41.5 v1(4422,184)
LMX2_SYNC: R277.2 R280.1 U24.7 | length 1269.4
  Bottom Layer w13.5: R277.2@1147,769.72 1147,662 1175.9,633.1 1565.24,633.1 1578.24,646.1 1578.24,682.1 1597.24,701.1 1648.24,701.1 1668.24,681.1 1668.24,416.1 1692.74,391.6 R280.1@1964,391.6
LMX2_SYSREFREQ: R132.2 R300.2 U24.6 | length 1280.4
  Bottom Layer w13.5: R132.2@888.09,737.12 925.22,737.12 958.85,703.49 958.85,632.49 997.85,593.49 1447.85,593.49 1699.35,341.99 1892.36,341.99 R300.2@1963.22,341.99
LMX_OSCIN1+: C71.2 U3.8 | length 142.5
  Top Layer w8: U3.8@1124.88,3302.76 1143.69,3302.76 1145.53,3304.6 1239.69,3304.6 C71.2@1258.75,3285.55
LMX_OSCIN1-: C72.2 U3.9 | length 141.3
  Top Layer w8: U3.9@1124.88,3322.44 1143.69,3322.44 1145.53,3320.6 1236.92,3320.6 C72.2@1257.05,3340.72
LMX_OSCIN2+: C104.2 U4.8 | length 142.5
  Top Layer w8: U4.8@1124.62,904.36 1143.43,904.36 1145.27,906.2 1239.43,906.2 C104.2@1257.99,887.64 C104.2@1258.49,887.14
